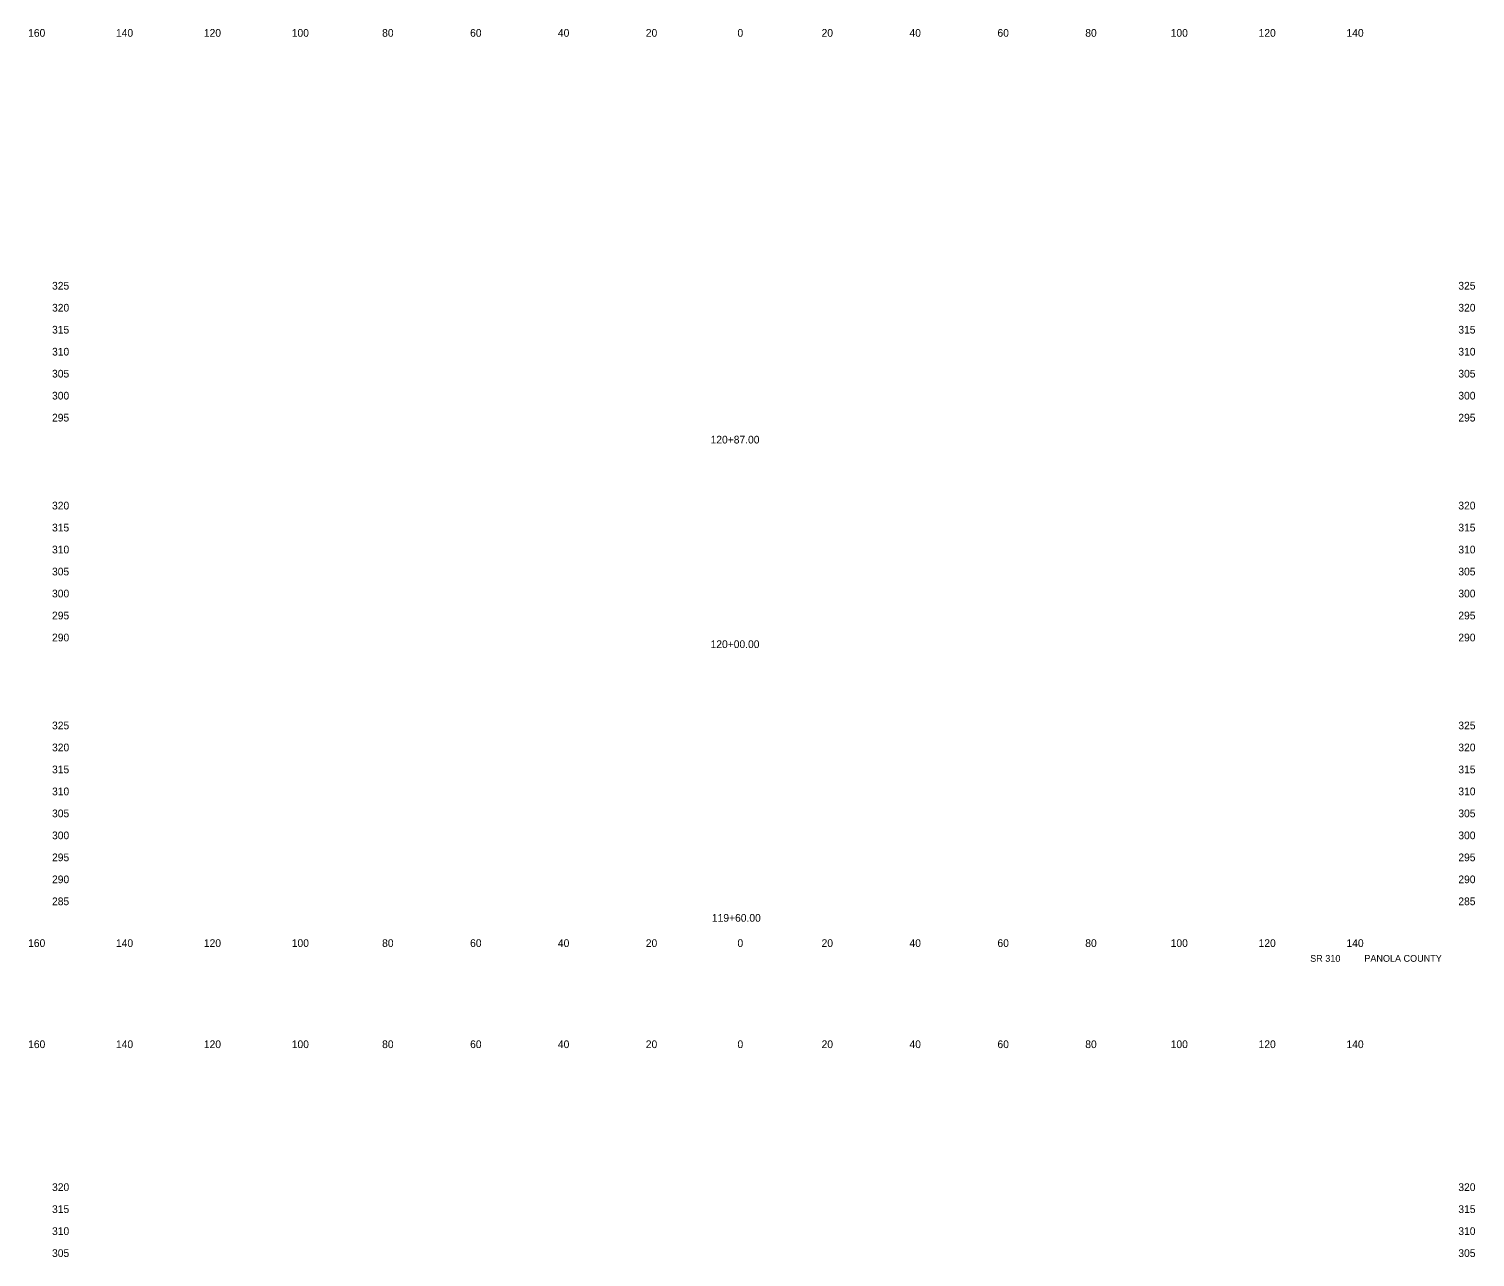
# Model space of a CAD drawing. Extents: x 21481 to 21810, y 6485 to 11067.
# Drawn here: x 21480.9 to 21809.9, y 8487.7 to 8767 of the extents above; entities that cross this region are included whole.
import ezdxf

# ---------------------------------------------------------------- set-up
doc = ezdxf.new("R2010")
doc.units = 0
for name, color, linetype in [('62', 7, 'Continuous'), ('XS_CELL', 7, 'Continuous'), ('XS_P_TX_DCH', 7, 'Continuous'), ('XS_P_TX_FS_BS', 7, 'Continuous')]:
    doc.layers.add(name, color=color, linetype=linetype)

msp = doc.modelspace()

# ---------------------------------------------------------------- texts
at = {"layer": '62'}
for s, p in [('  160  ', (21479.4, 8765.21)), ('  140  ', (21499.39, 8765.21)), ('  120  ', (21519.39, 8765.21)), ('  100  ', (21539.39, 8765.21)), ('  80  ', (21559.95, 8765.21)), ('  60  ', (21579.97, 8765.21)), ('  40  ', (21599.95, 8765.21)), ('  20  ', (21619.95, 8765.21)), ('  0  ', (21640.81, 8765.21)), ('  0  ', (21640.81, 8765.21)), ('  20  ', (21659.95, 8765.21)), ('  40  ', (21679.95, 8765.21)), ('  60  ', (21699.97, 8765.21)), ('  80  ', (21719.95, 8765.21)), ('  100  ', (21739.39, 8765.21)), ('  120  ', (21759.39, 8765.21)), ('  140  ', (21779.39, 8765.21)), ('  160  ', (21479.4, 8558.21)), ('  140  ', (21499.39, 8558.21)), ('  120  ', (21519.39, 8558.21)), ('  100  ', (21539.39, 8558.21)), ('  80  ', (21559.95, 8558.21)), ('  60  ', (21579.97, 8558.21)), ('  40  ', (21599.95, 8558.21)), ('  20  ', (21619.95, 8558.21)), ('  0  ', (21640.81, 8558.21)), ('  0  ', (21640.81, 8558.21)), ('  20  ', (21659.95, 8558.21)), ('  40  ', (21679.95, 8558.21)), ('  60  ', (21699.97, 8558.21)), ('  80  ', (21719.95, 8558.21)), ('  100  ', (21739.39, 8558.21)), ('  120  ', (21759.39, 8558.21)), ('  140  ', (21779.39, 8558.21)), ('  160  ', (21479.4, 8535.21)), ('  140  ', (21499.39, 8535.21)), ('  120  ', (21519.39, 8535.21)), ('  100  ', (21539.39, 8535.21)), ('  80  ', (21559.95, 8535.21)), ('  60  ', (21579.97, 8535.21)), ('  40  ', (21599.95, 8535.21)), ('  20  ', (21619.95, 8535.21)), ('  0  ', (21640.81, 8535.21)), ('  0  ', (21640.81, 8535.21)), ('  20  ', (21659.95, 8535.21)), ('  40  ', (21679.95, 8535.21)), ('  60  ', (21699.97, 8535.21)), ('  80  ', (21719.95, 8535.21)), ('  100  ', (21739.39, 8535.21)), ('  120  ', (21759.39, 8535.21)), ('  140  ', (21779.39, 8535.21))]:
    msp.add_text(s, height=1.75, dxfattribs=at).set_placement(p)
at = {"layer": 'XS_CELL'}
for s, p in [('  325  ', (21484.84, 8707.71)), ('  325  ', (21804.84, 8707.71)), ('  320  ', (21484.84, 8702.71)), ('  320  ', (21804.84, 8702.71)), ('  315  ', (21484.84, 8697.71)), ('  315  ', (21804.84, 8697.71)), ('  310  ', (21484.84, 8692.71)), ('  310  ', (21804.84, 8692.71)), ('  305  ', (21484.84, 8687.71)), ('  305  ', (21804.84, 8687.71)), ('  300  ', (21484.84, 8682.71)), ('  300  ', (21804.84, 8682.71)), ('  295  ', (21484.84, 8677.71)), ('  295  ', (21804.84, 8677.71)), ('  320  ', (21484.84, 8657.71)), ('  320  ', (21804.84, 8657.71)), ('  315  ', (21484.84, 8652.71)), ('  315  ', (21804.84, 8652.71)), ('  310  ', (21484.84, 8647.71)), ('  310  ', (21804.84, 8647.71)), ('  305  ', (21484.84, 8642.71)), ('  305  ', (21804.84, 8642.71)), ('  300  ', (21484.84, 8637.71)), ('  300  ', (21804.84, 8637.71)), ('  295  ', (21484.84, 8632.71)), ('  295  ', (21804.84, 8632.71)), ('  290  ', (21484.84, 8627.71)), ('  290  ', (21804.84, 8627.71)), ('  325  ', (21484.84, 8607.71)), ('  325  ', (21804.84, 8607.71)), ('  320  ', (21484.84, 8602.71)), ('  320  ', (21804.84, 8602.71)), ('  315  ', (21484.84, 8597.71)), ('  315  ', (21804.84, 8597.71)), ('  310  ', (21484.84, 8592.71)), ('  310  ', (21804.84, 8592.71)), ('  305  ', (21484.84, 8587.71)), ('  305  ', (21804.84, 8587.71)), ('  300  ', (21484.84, 8582.71)), ('  300  ', (21804.84, 8582.71)), ('  295  ', (21484.84, 8577.71)), ('  295  ', (21804.84, 8577.71)), ('  290  ', (21484.84, 8572.71)), ('  290  ', (21804.84, 8572.71)), ('  285  ', (21484.84, 8567.71)), ('  285  ', (21804.84, 8567.71)), ('  320  ', (21484.84, 8502.71)), ('  320  ', (21804.84, 8502.71)), ('  315  ', (21484.84, 8497.71)), ('  315  ', (21804.84, 8497.71)), ('  310  ', (21484.84, 8492.71)), ('  310  ', (21804.84, 8492.71)), ('  305  ', (21484.84, 8487.71)), ('  305  ', (21804.84, 8487.71))]:
    msp.add_text(s, height=1.75, dxfattribs=at).set_placement(p)
at = {"layer": 'XS_P_TX_DCH'}
for s, p in [('  120+87.00  ', (21634.69, 8672.71)), ('  120+00.00  ', (21634.69, 8626.19)), ('  119+60.00  ', (21634.99, 8563.95))]:
    msp.add_text(s, height=1.75, dxfattribs=at).set_placement(p)
at = {"layer": 'XS_P_TX_FS_BS'}
for s, p in [('SR 310', (21772.43, 8554.84)), ('SR 310', (21772.43, 8554.84)), ('SR 310', (21772.43, 8554.84)), ('PANOLA COUNTY', (21784.75, 8554.84)), ('PANOLA COUNTY', (21784.75, 8554.84)), ('PANOLA COUNTY', (21784.75, 8554.84))]:
    msp.add_text(s, height=1.54, dxfattribs=at).set_placement(p)

doc.saveas('drawing.dxf')
